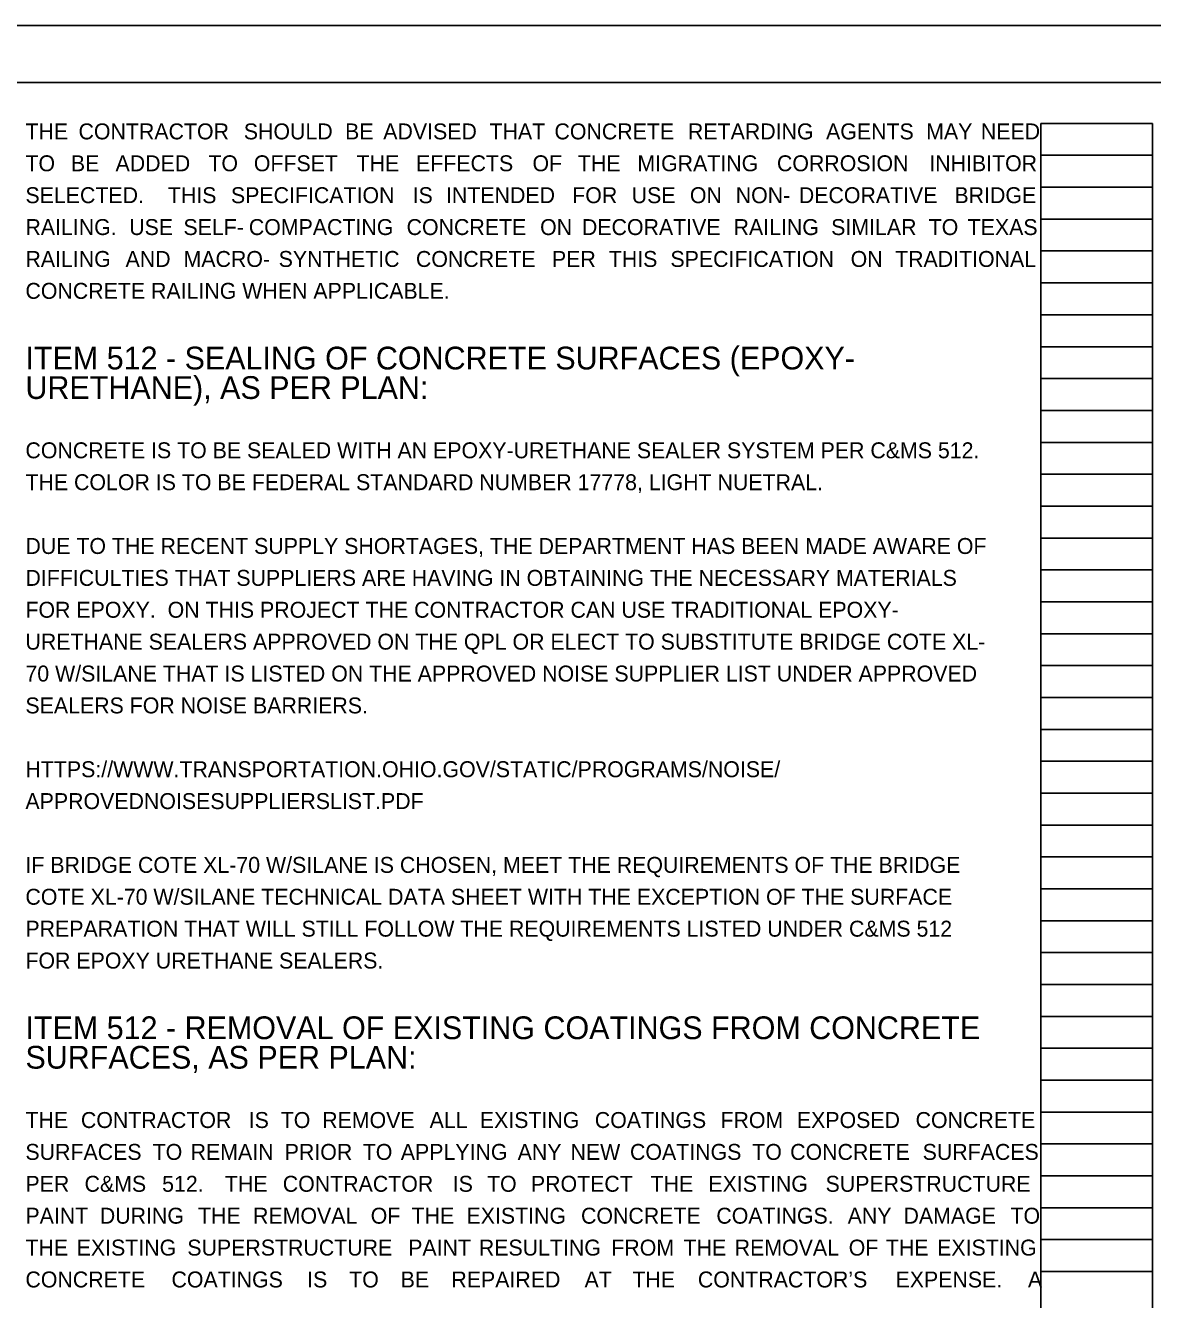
# Model space of a CAD drawing. Extents: x 0 to 34, y 0 to 22.
# Drawn here: x 12.29 to 22.19, y 10.81 to 22 of the extents above; entities that cross this region are included whole.
import ezdxf

# ---------------------------------------------------------------- set-up
doc = ezdxf.new("R2010")
doc.units = 0
for name, color, linetype in [('BR_P_Gen_Text', 7, 'Continuous'), ('SC_Scratch1', 7, 'Continuous'), ('SH_Border', 7, 'Continuous'), ('SH_Cut_Line', 7, 'Continuous'), ('SH_Text', 7, 'Continuous')]:
    doc.layers.add(name, color=color, linetype=linetype)

msp = doc.modelspace()

# ---------------------------------------------------------------- linework, layer by layer
at = {"layer": 'SC_Scratch1'}
for p, q in [((21.207, 0.98), (21.207, 21.14)), ((21.207, 21.14), (22.187, 21.14)), ((22.187, 0.98), (22.187, 21.14)), ((21.207, 20.86), (22.187, 20.86)), ((21.207, 20.58), (22.187, 20.58)), ((21.207, 20.3), (22.187, 20.3)), ((21.207, 20.02), (22.187, 20.02)), ((21.207, 19.74), (22.187, 19.74)), ((21.207, 19.46), (22.187, 19.46)), ((21.207, 19.18), (22.187, 19.18)), ((21.207, 18.9), (22.187, 18.9)), ((21.207, 18.62), (22.187, 18.62)), ((21.207, 18.34), (22.187, 18.34)), ((21.207, 18.06), (22.187, 18.06)), ((21.207, 17.78), (22.187, 17.78)), ((21.207, 17.5), (22.187, 17.5)), ((21.207, 17.22), (22.187, 17.22)), ((21.207, 16.94), (22.187, 16.94)), ((21.207, 16.66), (22.187, 16.66)), ((21.207, 16.38), (22.187, 16.38)), ((21.207, 16.1), (22.187, 16.1)), ((21.207, 15.82), (22.187, 15.82)), ((21.207, 15.54), (22.187, 15.54)), ((21.207, 15.26), (22.187, 15.26)), ((21.207, 14.98), (22.187, 14.98)), ((21.207, 14.7), (22.187, 14.7)), ((21.207, 14.42), (22.187, 14.42)), ((21.207, 14.14), (22.187, 14.14)), ((21.207, 13.86), (22.187, 13.86)), ((21.207, 13.58), (22.187, 13.58)), ((21.207, 13.3), (22.187, 13.3)), ((21.207, 13.02), (22.187, 13.02)), ((21.207, 12.74), (22.187, 12.74)), ((21.207, 12.46), (22.187, 12.46)), ((21.207, 12.18), (22.187, 12.18)), ((21.207, 11.9), (22.187, 11.9)), ((21.207, 11.62), (22.187, 11.62)), ((21.207, 11.34), (22.187, 11.34)), ((21.207, 11.06), (22.187, 11.06))]:
    msp.add_line(p, q, dxfattribs=at)
msp.add_lwpolyline([(0, 22), (34, 22), (34, 0), (0, 0)], close=True, dxfattribs=at)
at = {"layer": 'SH_Border'}
msp.add_lwpolyline([(1.5, 21.5), (33.5, 21.5), (33.5, 0.5), (1.5, 0.5)], close=True, dxfattribs=at)
at = {"layer": 'SH_Cut_Line'}
msp.add_lwpolyline([(0, 0), (34, 0), (34, 22), (0, 22)], close=True, dxfattribs=at)

# ---------------------------------------------------------------- texts
at = {"layer": 'BR_P_Gen_Text'}
for s, p in [('ITEM 512 - SEALING OF CONCRETE SURFACES (EPOXY-', (12.293, 18.98)), ('URETHANE), AS PER PLAN:', (12.293, 18.721)), ('ITEM 512 - REMOVAL OF EXISTING COATINGS FROM CONCRETE ', (12.293, 13.1)), ('SURFACES, AS PER PLAN:', (12.293, 12.841))]:
    msp.add_text(s, height=0.2, dxfattribs=at).set_placement(p)
at = {"layer": 'SH_Text'}
for s, p in [('CONTRACTOR ', (12.759, 21)), ('SHOULD ', (14.21, 21)), ('ADVISED ', (15.434, 21)), ('CONCRETE ', (16.937, 21)), ('RETARDING ', (18.109, 21)), ('AGENTS ', (19.321, 21)), ('THE ', (12.293, 21)), ('BE ', (15.099, 21)), ('THAT ', (16.367, 21)), ('MAY ', (20.2, 21)), ('NEED ', (20.68, 21)), ('TO ', (12.293, 20.72)), ('BE ', (12.692, 20.72)), ('ADDED ', (13.084, 20.72)), ('TO ', (13.899, 20.72)), ('OFFSET ', (14.298, 20.72)), ('THE ', (15.2, 20.72)), ('EFFECTS ', (15.722, 20.72)), ('OF ', (16.744, 20.72)), ('THE ', (17.143, 20.72)), ('MIGRATING ', (17.665, 20.72)), ('CORROSION ', (18.89, 20.72)), ('INHIBITOR ', (20.227, 20.72)), ('SELECTED.  ', (12.293, 20.44)), ('THIS ', (13.543, 20.44)), ('SPECIFICATION ', (14.097, 20.44)), ('IS ', (15.692, 20.44)), ('INTENDED ', (15.985, 20.44)), ('FOR ', (17.093, 20.44)), ('USE ', (17.615, 20.44)), ('ON ', (18.126, 20.44)), ('NON-', (18.528, 20.44)), ('DECORATIVE ', (19.082, 20.44)), ('BRIDGE ', (20.448, 20.44)), ('RAILING. ', (12.293, 20.16)), ('USE ', (13.204, 20.16)), ('SELF-', (13.68, 20.16)), ('COMPACTING ', (14.254, 20.16)), ('CONCRETE ', (15.639, 20.16)), ('ON ', (16.811, 20.16)), ('DECORATIVE ', (17.178, 20.16)), ('RAILING ', (18.509, 20.16)), ('SIMILAR ', (19.366, 20.16)), ('TO ', (20.222, 20.16)), ('TEXAS ', (20.564, 20.16)), ('RAILING ', (12.293, 19.88)), ('AND ', (13.172, 19.88)), ('MACRO-', (13.681, 19.88)), ('SYNTHETIC ', (14.516, 19.88)), ('CONCRETE ', (15.721, 19.88)), ('PER ', (16.915, 19.88)), ('THIS ', (17.414, 19.88)), ('SPECIFICATION ', (17.955, 19.88)), ('ON ', (19.537, 19.88)), ('TRADITIONAL ', (19.927, 19.88)), ('CONCRETE RAILING WHEN APPLICABLE.', (12.293, 19.6)), ('CONCRETE IS TO BE SEALED WITH AN EPOXY-URETHANE SEALER SYSTEM PER C&MS 512. ', (12.293, 18.2)), ('THE COLOR IS TO BE FEDERAL STANDARD NUMBER 17778, LIGHT NUETRAL. ', (12.293, 17.92)), ('DUE TO THE RECENT SUPPLY SHORTAGES, THE DEPARTMENT HAS BEEN MADE AWARE OF ', (12.293, 17.36)), ('DIFFICULTIES THAT SUPPLIERS ARE HAVING IN OBTAINING THE NECESSARY MATERIALS ', (12.293, 17.08)), ('FOR EPOXY.  ON THIS PROJECT THE CONTRACTOR CAN USE TRADITIONAL EPOXY-', (12.293, 16.8)), ('URETHANE SEALERS APPROVED ON THE QPL OR ELECT TO SUBSTITUTE BRIDGE COTE XL-', (12.293, 16.52)), ('70 W/SILANE THAT IS LISTED ON THE APPROVED NOISE SUPPLIER LIST UNDER APPROVED ', (12.293, 16.24)), ('SEALERS FOR NOISE BARRIERS.  ', (12.293, 15.96)), ('HTTPS://WWW.TRANSPORTATION.OHIO.GOV/STATIC/PROGRAMS/NOISE/', (12.293, 15.4)), ('APPROVEDNOISESUPPLIERSLIST.PDF ', (12.293, 15.12)), ('IF BRIDGE COTE XL-70 W/SILANE IS CHOSEN, MEET THE REQUIREMENTS OF THE BRIDGE ', (12.293, 14.56)), ('COTE XL-70 W/SILANE TECHNICAL DATA SHEET WITH THE EXCEPTION OF THE SURFACE ', (12.293, 14.28)), ('PREPARATION THAT WILL STILL FOLLOW THE REQUIREMENTS LISTED UNDER C&MS 512 ', (12.293, 14)), ('FOR EPOXY URETHANE SEALERS.', (12.293, 13.72)), ('THE ', (12.293, 12.32)), ('CONTRACTOR ', (12.78, 12.32)), ('IS ', (14.253, 12.32)), ('TO ', (14.534, 12.32)), ('REMOVE ', (14.898, 12.32)), ('ALL ', (15.841, 12.32)), ('EXISTING ', (16.282, 12.32)), ('COATINGS ', (17.291, 12.32)), ('FROM ', (18.394, 12.32)), ('EXPOSED ', (19.065, 12.32)), ('CONCRETE ', (20.107, 12.32)), ('SURFACES ', (12.293, 12.04)), ('TO ', (13.41, 12.04)), ('REMAIN ', (13.743, 12.04)), ('PRIOR ', (14.569, 12.04)), ('TO ', (15.254, 12.04)), ('APPLYING ', (15.588, 12.04)), ('ANY ', (16.614, 12.04)), ('NEW ', (17.078, 12.04)), ('COATINGS ', (17.6, 12.04)), ('TO ', (18.673, 12.04)), ('CONCRETE ', (19.006, 12.04)), ('SURFACES ', (20.169, 12.04)), ('PER ', (12.293, 11.76)), ('C&MS ', (12.812, 11.76)), ('512.  ', (13.493, 11.76)), ('THE ', (14.044, 11.76)), ('CONTRACTOR ', (14.552, 11.76)), ('IS ', (16.044, 11.76)), ('TO ', (16.345, 11.76)), ('PROTECT ', (16.73, 11.76)), ('THE ', (17.781, 11.76)), ('EXISTING ', (18.288, 11.76)), ('SUPERSTRUCTURE ', (19.317, 11.76)), ('PAINT ', (12.293, 11.48)), ('DURING ', (12.946, 11.48)), ('THE ', (13.808, 11.48)), ('REMOVAL ', (14.291, 11.48)), ('OF ', (15.324, 11.48)), ('THE ', (15.683, 11.48)), ('EXISTING ', (16.165, 11.48)), ('CONCRETE ', (17.17, 11.48)), ('COATINGS. ', (18.358, 11.48)), ('ANY ', (19.511, 11.48)), ('DAMAGE ', (20.001, 11.48)), ('TO ', (20.94, 11.48)), ('THE ', (12.293, 11.2)), ('EXISTING ', (12.743, 11.2)), ('SUPERSTRUCTURE ', (13.714, 11.2)), ('PAINT ', (15.653, 11.2)), ('RESULTING ', (16.273, 11.2)), ('FROM ', (17.436, 11.2)), ('THE ', (18.07, 11.2)), ('REMOVAL ', (18.519, 11.2)), ('OF ', (19.52, 11.2)), ('THE ', (19.846, 11.2)), ('EXISTING ', (20.296, 11.2)), ('CONCRETE ', (12.293, 10.92)), ('COATINGS ', (13.575, 10.92)), ('IS ', (14.766, 10.92)), ('TO ', (15.135, 10.92)), ('BE ', (15.587, 10.92)), ('REPAIRED ', (16.032, 10.92)), ('AT ', (17.201, 10.92)), ('THE ', (17.621, 10.92)), ('CONTRACTOR’S ', (18.196, 10.92)), ('EXPENSE. ', (19.931, 10.92)), ('A ', (21.093, 10.92))]:
    msp.add_text(s, height=0.14, dxfattribs=at).set_placement(p)

doc.saveas('drawing.dxf')
